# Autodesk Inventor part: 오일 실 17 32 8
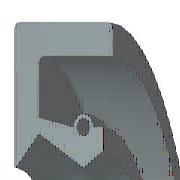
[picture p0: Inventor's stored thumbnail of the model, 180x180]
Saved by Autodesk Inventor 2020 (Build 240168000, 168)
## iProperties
IsCustomPart: 1
Created: 2012-02
Part Number: 오일 실 17 32 8
Material: 고무
Description: 오일-실
Document SubType Name: Modeling
Standard: KS B 2804
Designer: mduedu
Standards Organization: KS
Language: ko-KR
Size Designation: D - 17 32 8
Categories: <MemberInstance><Categories><Category DisplayName="샤프트 부품" InternalName="7f7aeb1f-a693-4053-b835-cee3144e0d98" Mnemonic="SHFT"><Category DisplayName="실링" Intern
Density: 0.93 g/cm^3
Appearance: 고무 - 검은색 - 버전 1.1
Author: mduedu
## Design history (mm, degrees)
revolve "본체" stored, may be unused: angle "d17" = 90 deg
revolve "스프링1" stored, may be unused: angle "d18" = 90 deg
body "Solid1"
sketch "스케치1"
  geometry: L1 (0, 16)-(8, 16); L2 (8, 14.25)-(1.75, 14.25); L3 (1.75, 10.25)-(4.9, 8.5); L4 (4.9, 8.5)-(0, 8.5); L5 (0, 0)-(9.586, 0) reference; L6 (4.9, 8.5)-(6.3, 9.375); L7 (0, 18)-(0, -3) reference; L8 (-1.941, 0)-(11.507, 0) reference; L9 (4.2, 10.6)-(1.75, 11.21); L10 (1.75, 11.21)-(1.75, 14.25); L11 (0, 16)-(0, 8.588); L12 (4.9, 8.5)-(0, 8.5); L13 (1.75, 10.25)-(0.152, 8.528); L14 (8, 16)-(8, 14.25); L15 (5.6, 10.6)-(6.3, 10.6); L16 (6.3, 10.6)-(6.3, 9.375); C1 r 0.455 at (4.9, 10.6); A1 r 0.7 centre (4.9, 10.6) between (5.6, 10.6) and (4.2, 10.6); A2 r 0.088 centre (0.088, 8.588) between (0, 8.588) and (0.152, 8.528); 1 further point
  constraints: 28 end point, 5 horizontal alignment, 5 point on line, 4 point on circle, 4 vertical alignment, 3 centre point, 3 tangent, 2 collinear, 2 horizontal, 2 perpendicular, 1 coincident, 1 parallel
  dimensions: "d0" = 32 diameter of L1 L5 (= SD2); "d1" = 1.75 distance of L1.end L2.start (= SD); "d2" = 0.91 diameter of C1 (= SPDI); "d3" = 1.4 diameter of A1 (= SPDA); "d4" = 17 diameter of L3.end L5 (= NND); "d5" = 20.5 diameter of L3.start L5 (= TKDM); "d7" = 22.42 diameter of L9.end L5 (= TKDM + 0.24 x SWDT); "d8" = 1.75 distance between parallel lines of L11 L10 (= SD); "d9" = 4.9 distance from line of L11 C1.centre (= SPDST); "d10" = 21.2 diameter of C1.centre L5 (= HLDM); "d11" = 0.0875 radius of A2 (= 0.25 x LAB); "d12" = 6.3 distance between parallel lines of L11 L16 (= SDI); "d13" = 18.75 diameter of L6.end L5 (= ABDM); "d14" = 8 distance from line of L11 L1.end (= SWDT)
fillet "모깎기1" dims "d6" = 0.3 (= RR)
other parameters: "SD2" = 32 [user parameter; used in 1 equation term], "SWDT" = 8 [user parameter; used in 2 equation terms], "RR" = 0.3 [user parameter; used in 1 equation term], "SD" = 1.75 [user parameter; used in 2 equation terms], "NND" = 17 [user parameter; used in 1 equation term], "SPDA" = 1.4 [user parameter; used in 1 equation term], "SPDI" = 0.91 [user parameter; used in 1 equation term], "TKDM" = 20.5 [user parameter; used in 2 equation terms], "HLDM" = 21.2 [user parameter; used in 1 equation term], "ABDM" = 18.75 [user parameter; used in 1 equation term], "SDI" = 6.3 [user parameter; used in 1 equation term], "SPDST" = 4.9 [user parameter; used in 1 equation term], "LAB" = 0.35 [user parameter; used in 1 equation term], "d15" = 0, "d16" = 0, "d19" = 0
